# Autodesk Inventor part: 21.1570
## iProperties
Created: 2012-02
Part Number: 21.1570
Document SubType Name: Modeling
Designer: Administrator
Density: 7.85 g/cm^3
Material: Steel
Mass: 4.29634 g
Surface Area: 8.53533 cm^2
Volume: 0.547304 cm^3
Description: M8 SQUARE NUT 30
Vendor: S
Author: Administrator
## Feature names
1. Extrusion1
2. Extrusion2
3. Fillet1
4. Hole1
5. Extrusion3
6. Extrusion4
7. Fillet2
